// Mitsubishi GX Works2 project: Vol5_Robot_PLC   PLC: Q06UDEH

PROGRAM MAIN
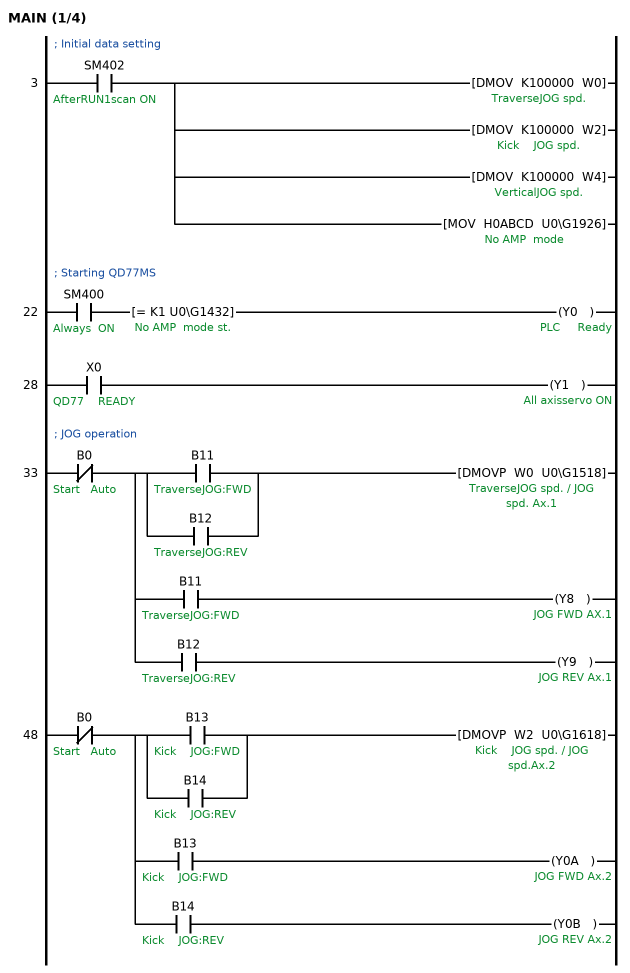
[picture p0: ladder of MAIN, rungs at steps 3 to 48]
; 
; Initial data setting
; 
3     LD      SM402  ; AfterRUN1scan ON
      DMOV    K100000 W0  ; TraverseJOG spd.
        [note] JOG speed set : x0.01mm/min
      DMOV    K100000 W2  ; Kick    JOG spd.
      DMOV    K100000 W4  ; VerticalJOG spd.
      MOV     H0ABCD U0\G1926  ; No AMP  mode
        [note] No Amp mode setting
; 
; Starting QD77MS
; 
22    LD      SM400  ; Always  ON
      AND=    K1 U0\G1432  ; No AMP  mode st.
      OUT     Y0  ; PLC     Ready
28    LD      X0  ; QD77    READY
      OUT     Y1  ; All axisservo ON
; 
; JOG operation
; 
33    LDI     B0  ; Start   Auto
      MPS
      LD      B11  ; TraverseJOG:FWD
      OR      B12  ; TraverseJOG:REV
      ANB
      DMOVP   W0 U0\G1518  ; JOG spd. Ax.1
      MRD
      AND     B11  ; TraverseJOG:FWD
      OUT     Y8  ; JOG FWD AX.1
      MPP
      AND     B12  ; TraverseJOG:REV
      OUT     Y9  ; JOG REV Ax.1
48    LDI     B0  ; Start   Auto
      MPS
      LD      B13  ; Kick    JOG:FWD
      OR      B14  ; Kick    JOG:REV
      ANB
      DMOVP   W2 U0\G1618  ; JOG spd.Ax.2
      MRD
      AND     B13  ; Kick    JOG:FWD
      OUT     Y0A  ; JOG FWD Ax.2
      MPP
      AND     B14  ; Kick    JOG:REV
      OUT     Y0B  ; JOG REV Ax.2
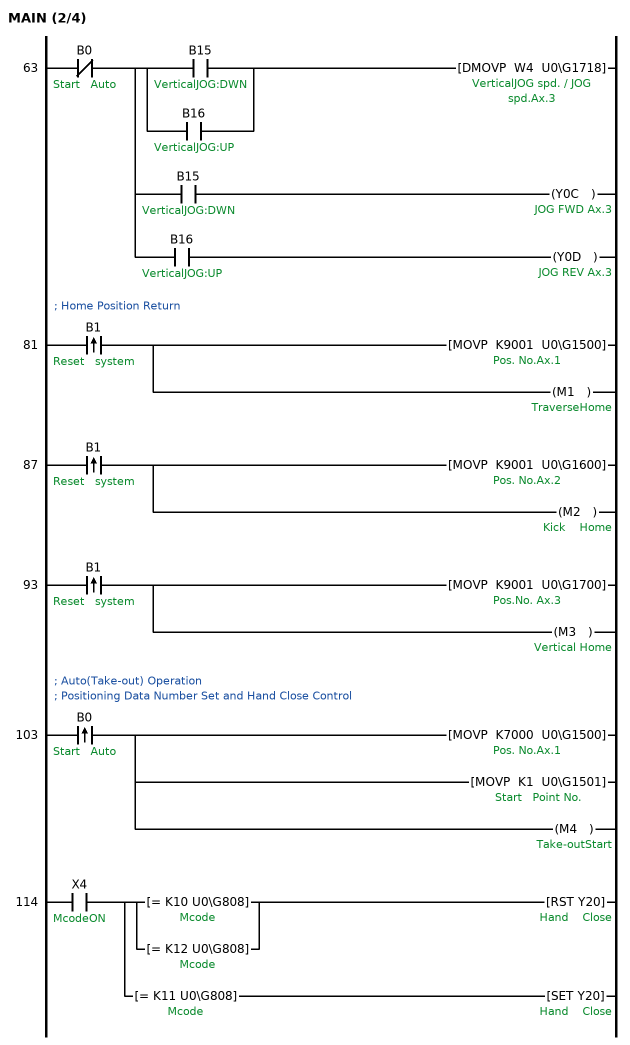
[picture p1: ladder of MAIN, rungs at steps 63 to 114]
63    LDI     B0  ; Start   Auto
      MPS
      LD      B15  ; VerticalJOG:DWN
      OR      B16  ; VerticalJOG:UP
      ANB
      DMOVP   W4 U0\G1718  ; JOG spd.Ax.3
      MRD
      AND     B15  ; VerticalJOG:DWN
      OUT     Y0C  ; JOG FWD Ax.3
      MPP
      AND     B16  ; VerticalJOG:UP
      OUT     Y0D  ; JOG REV Ax.3
; 
; Home Position Return
; 
81    LDP     B1  ; Reset   system
      MOVP    K9001 U0\G1500  ; Pos. No.Ax.1
      OUT     M1  ; TraverseHome
87    LDP     B1  ; Reset   system
      MOVP    K9001 U0\G1600  ; Pos. No.Ax.2
      OUT     M2  ; Kick    Home
93    LDP     B1  ; Reset   system
      MOVP    K9001 U0\G1700  ; Pos.No. Ax.3
      OUT     M3  ; Vertical Home
; 
; Auto(Take-out) Operation
; Positioning Data Number Set and Hand Close Control
; 
103   LDP     B0  ; Start   Auto
      MOVP    K7000 U0\G1500
        [note] Positioning Data Number Set
      MOVP    K1 U0\G1501  ; Start   Point No.
      OUT     M4  ; Take-outStart
114   LD      X4  ; McodeON
      MPS
      LD=     K10 U0\G808  ; Mcode
      OR=     K12 U0\G808  ; Mcode
      ANB
      RST     Y20  ; Hand    Close
        [note] Hand Open/Close Control
      MPP
      AND=    K11 U0\G808  ; Mcode
      SET     Y20  ; Hand    Close
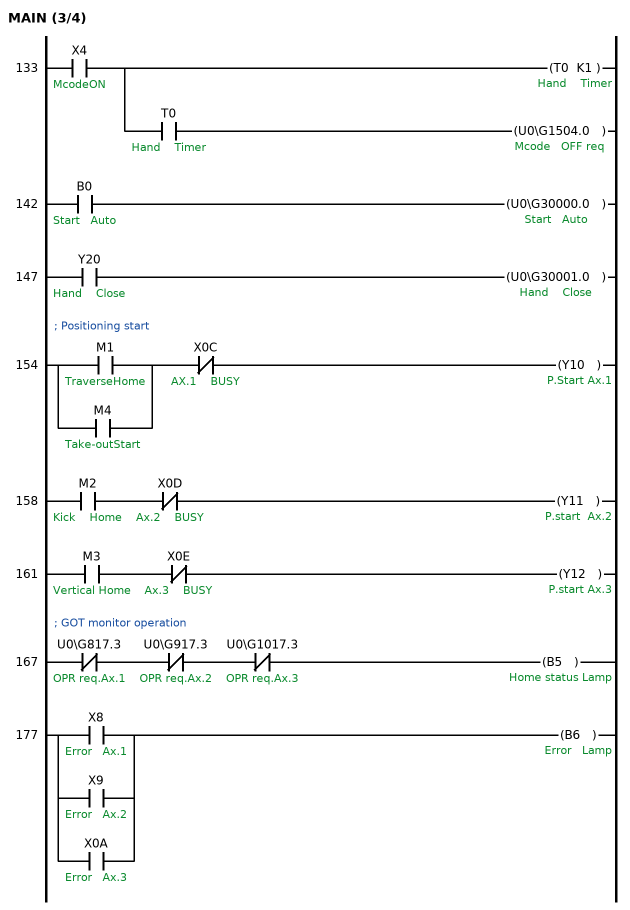
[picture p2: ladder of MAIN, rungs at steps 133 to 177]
133   LD      X4  ; McodeON
      OUT     T0 K1  ; Hand    Timer
      AND     T0  ; Hand    Timer
      OUT     U0\G1504.0  ; Mcode   OFF req
142   LD      B0  ; Start   Auto
      OUT     U0\G30000.0  ; Start   Auto
        [note] For Oscillo Data Sampling
147   LD      Y20  ; Hand    Close
      OUT     U0\G30001.0  ; Hand    Close
; 
; Positioning start
; 
154   LD      M1  ; TraverseHome
      OR      M4  ; Take-outStart
      ANI     X0C  ; AX.1    BUSY
      OUT     Y10  ; P.Start Ax.1
158   LD      M2  ; Kick    Home
      ANI     X0D  ; Ax.2    BUSY
      OUT     Y11  ; P.start  Ax.2
161   LD      M3  ; Vertical Home
      ANI     X0E  ; Ax.3    BUSY
      OUT     Y12  ; P.start Ax.3
; 
; GOT monitor operation
; 
167   LDI     U0\G817.3  ; OPR req.Ax.1
      ANI     U0\G917.3  ; OPR req.Ax.2
      ANI     U0\G1017.3  ; OPR req.Ax.3
      OUT     B5  ; Home status Lamp
177   LD      X8  ; Error   Ax.1
      OR      X9  ; Error   Ax.2
      OR      X0A  ; Error   Ax.3
      OUT     B6  ; Error   Lamp
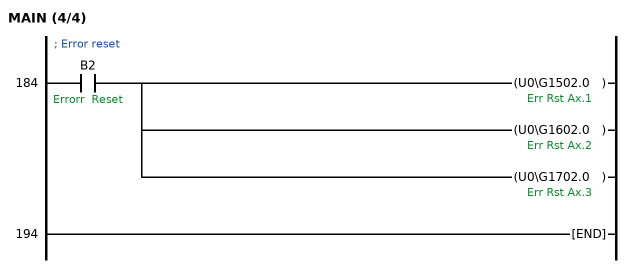
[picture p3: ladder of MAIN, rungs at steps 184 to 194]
; 
; Error reset
; 
184   LD      B2  ; Errorr  Reset
      OUT     U0\G1502.0  ; Err Rst Ax.1
      OUT     U0\G1602.0  ; Err Rst Ax.2
      OUT     U0\G1702.0  ; Err Rst Ax.3
194   END
END_PROGRAM

// device comments not shown above
Y5  ; Stop cmd Ax.2
Y6  ; Stop cmdAx.3(V)
Y13  ; P.start Ax.4
Y14  ; P.start Ax.5
Y15  ; Axis 6Positioning start
Y16  ; Axis 7Positioning start
Y17  ; Axis 8Positioning start
Y18  ; P.start Ax.9(V)
Y19  ; P.start Ax.10(V)
Y1A  ; Axis11Positioning start
Y1B  ; Axis12Positioning start
Y1C  ; Axis13Positioning start
Y1D  ; Axis14Positioning start
Y1E  ; Axis15Positioning start
Y1F  ; Axis16Positioning start
X1  ; Synchronization flag
X0F  ; Ax.4    BUSY
X10  ; Axis 1  BUSY
X11  ; Axis 2  BUSY
X12  ; Axis 3  BUSY
X13  ; Axis 4  BUSY
X14  ; Axis 5  BUSY
X15  ; Axis 6  BUSY
X16  ; Axis 7  BUSY
X17  ; Axis 8  BUSY
X18  ; Axis 9  BUSY
X19  ; Axis 10 BUSY
X1A  ; Axis 11 BUSY
X1B  ; Axis 12 BUSY
X1C  ; Axis 13 BUSY
X1D  ; Axis 14 BUSY
X1E  ; Axis 15 BUSY
X1F  ; Axis 16 BUSY
B3  ; Forced  Stop
B4  ; Mark Correction
B41  ; Sealer  JOG FWD
B42  ; Sealer  JOG REV
B51  ; ConveyorJOG FWD
B52  ; ConveyorJOG REV
W6  ; ConveyorJOG spd.
W0A  ; Product Counter
W10  ; Sheet  Lx 0.1mm
W12  ; Line Spd0.1m/min
W14  ; Seal stroke mm
W16  ; Sealing time ms
W20  ; Roll DIAmm
W24  ; Monitor pos. Ax2
W28  ; Monitor pos. Ax3
W2C  ; Monitor pos.Ax4
W30  ; Monitor spd. Ax5
D0  ; MarkCoutLastValue
D2  ; MarkDataLastValue
D4  ; Mark    betweenL
D6  ; Mark adjvalue
D100  ; Last ValCutPoint
D104  ; MarkSen.ON Adr.
D106  ; MarkSen.OFF Adr.
D108  ; LastTimeMarkData
D1000  ; Cycle   time ms
D1002  ; Seal travel time
D1004  ; Cam 1cycTime ms
D1006  ; Cam 1cycspd.
D1050  ; calc.   temp
